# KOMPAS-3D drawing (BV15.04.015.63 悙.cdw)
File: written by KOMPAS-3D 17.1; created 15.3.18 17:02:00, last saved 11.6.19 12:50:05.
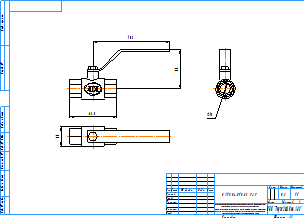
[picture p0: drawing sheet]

Sheet 1: A3, landscape

Title block, sheet 1: name: BV15.04.015.63 Р/Р; material: Внимание! Данный продукт является объектом авторского права ООО «Торговый Дом АДЛ». / Запрещается изменение, копирование, распространение / (в том числе путем копирования на другие сайты и ресурсы в Интернете) / или любое иное использование информации и объектов без предварительного / согласия правообладателя (ООО «Торговый Дом АДЛ»).; mass: 0,3; sheets: 1; organisation: ООО "Торговый дом АДЛ"; sheet format: A3; stored path: \\adlc.lan\data\АДЛ_ПКД\3D-модели\ADL production\Краны шаровые серии BV\BV15\KOMPAS 2D\BV15.04.015.63 РР.cdw

Views: Вид 1, Проекционный вид 2, Проекционный вид 3
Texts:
  kka
  adl
Dimensions and other numbers on the sheet: 63,5; 103; 53; 15; 27; 1:1; 1; 0,3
